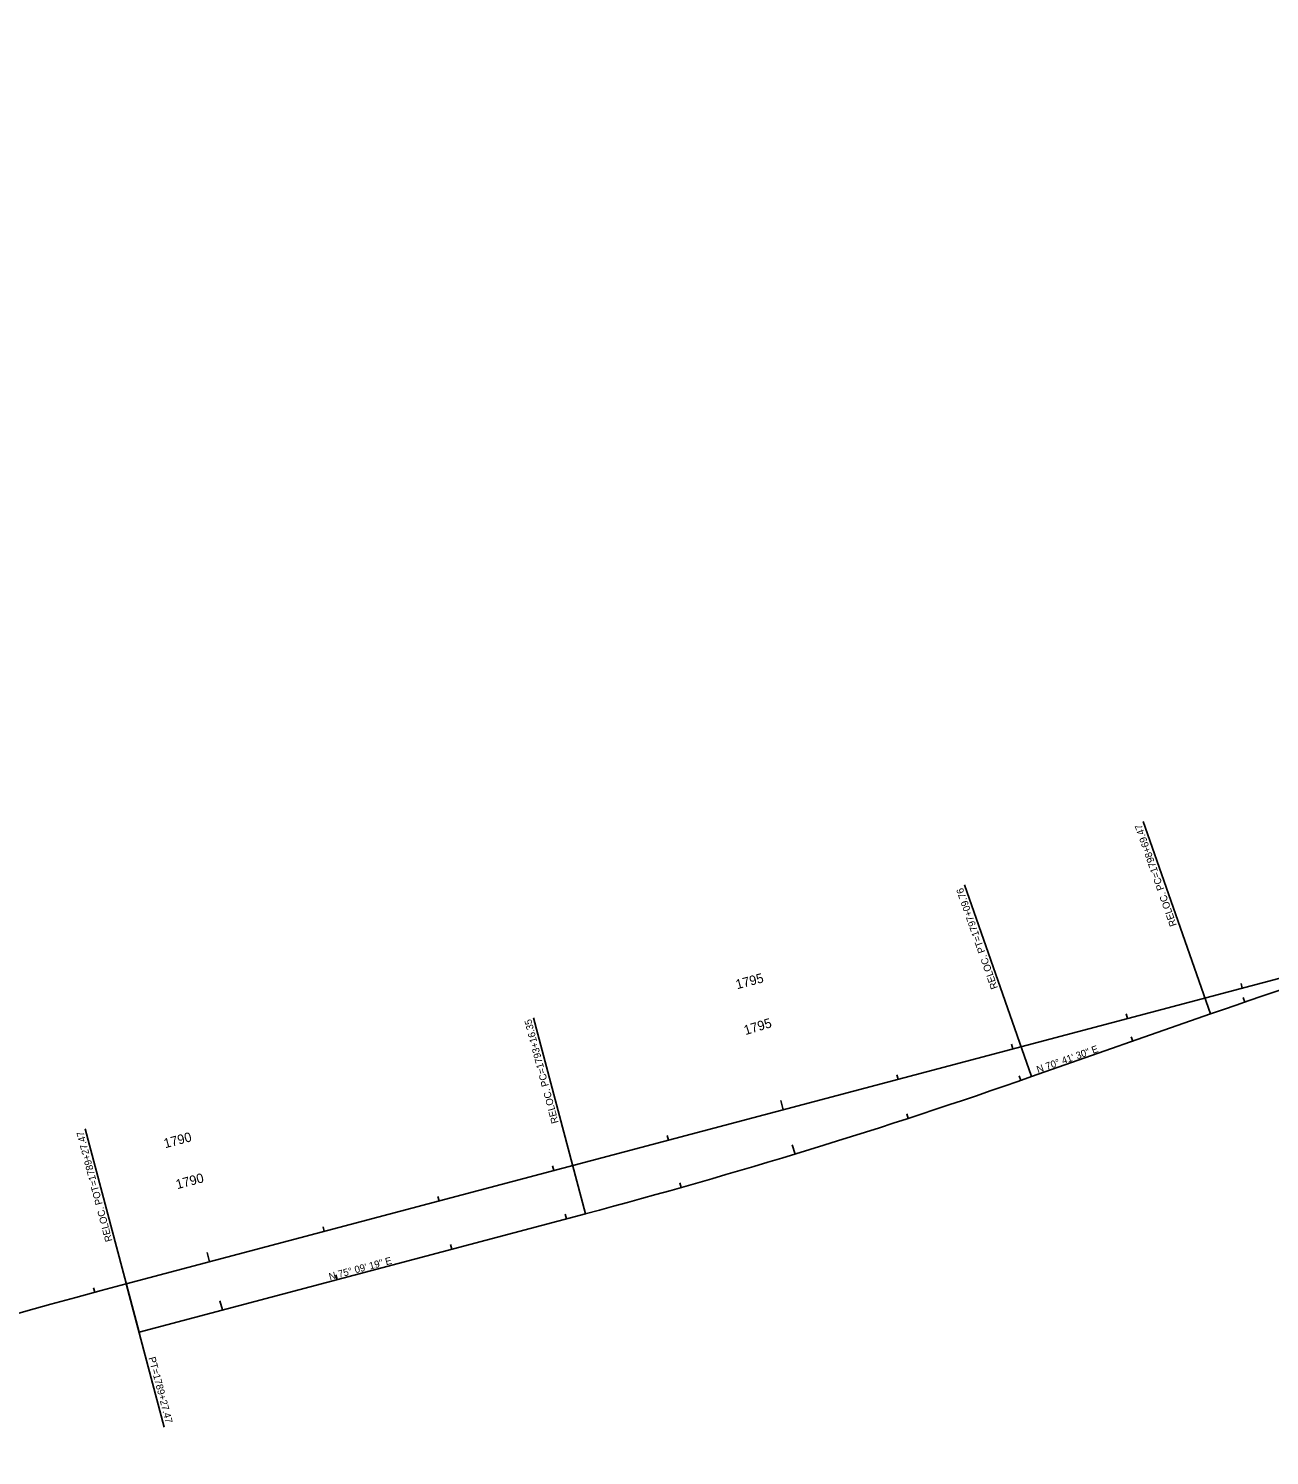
# Model space of a CAD drawing. Extents: x 2106154 to 2121963, y 864504 to 868517.
# Drawn here: x 2110006 to 2111052, y 867008 to 868210 of the extents above; entities that cross this region are included whole.
import ezdxf

# ---------------------------------------------------------------- set-up
doc = ezdxf.new("R2010")
doc.units = 0
for name, color, linetype in [('RD_HC_CL_Rel', 7, 'Continuous'), ('RD_HC_Data_Tic_Rel', 7, 'Continuous'), ('RD_HC_TX_Rel_Sta50', 7, 'Continuous'), ('RD_PD_EarthShd', 7, 'Continuous'), ('RD_PD_EOP', 7, 'Continuous'), ('RD_PD_Final_LnLine', 7, 'Continuous'), ('RD_Sketch1', 7, 'Continuous'), ('RD_Sketch10', 7, 'Continuous')]:
    doc.layers.add(name, color=color, linetype=linetype)

msp = doc.modelspace()

# ---------------------------------------------------------------- linework, layer by layer
at = {"layer": 'RD_HC_CL_Rel'}
msp.add_line((2110088.7, 867152.7), (2110120.7, 867032.1), dxfattribs=at)
at = {"layer": 'RD_HC_Data_Tic_Rel'}
for p, q in [((2110851.3, 867327.3), (2111002.1, 867380.1)), ((2110099.5, 867112.1), (2110475.4, 867211.8))]:
    msp.add_line(p, q, dxfattribs=at)
for centre, radius, start, end in [((2112556.1, 862944.4), 4700, 104.8448, 109.3083), ((2109181.5, 872093.2), 5050, 284.8448, 289.3083)]:
    msp.add_arc(centre, radius, start, end, dxfattribs=at)
at = {"layer": 'RD_HC_TX_Rel_Sta50'}
for p, q in [((2111002.1, 867380.1), (2110945.3, 867542.1)), ((2110851.3, 867327.3), (2110794.8, 867488.7)), ((2110475.4, 867211.8), (2110431.6, 867376.8)), ((2110099.5, 867112.1), (2110054.1, 867283.2))]:
    msp.add_line(p, q, dxfattribs=at)
at = {"layer": 'RD_PD_EarthShd'}
for p, q in [((2111028.8, 867401.9), (2111027.8, 867405.8)), ((2110932.1, 867376.3), (2110931.1, 867380.1)), ((2110835.5, 867350.7), (2110834.4, 867354.5)), ((2110738.8, 867325), (2110737.8, 867328.9)), ((2110642.1, 867299.4), (2110640.1, 867307.1)), ((2110545.5, 867273.8), (2110544.4, 867277.7)), ((2110448.8, 867248.2), (2110447.8, 867252)), ((2110352.1, 867222.6), (2110351.1, 867226.4)), ((2110255.5, 867196.9), (2110254.5, 867200.8)), ((2110158.8, 867171.3), (2110156.8, 867179)), ((2110062.2, 867145.6), (2110061.1, 867149.5))]:
    msp.add_line(p, q, dxfattribs=at)
at = {"layer": 'RD_PD_EOP'}
msp.add_line((2110088.7, 867152.7), (2114077.7, 868210), dxfattribs=at)
msp.add_arc((2111556.6, 861614.4), 5729.6, 104.84478, 132.83574, dxfattribs=at)
at = {"layer": 'RD_Sketch1'}
for p, q in [((2111030.9, 867390.1), (2111029.6, 867393.9)), ((2110936.5, 867357.1), (2110935.2, 867360.9)), ((2110842.1, 867324), (2110840.8, 867327.8)), ((2110747.4, 867292.1), (2110746.1, 867295.9)), ((2110652, 867262), (2110649.7, 867269.7)), ((2110556, 867233.9), (2110555, 867237.7)), ((2110459.6, 867207.6), (2110458.5, 867211.4)), ((2110362.9, 867182), (2110361.9, 867185.8)), ((2110266.2, 867156.3), (2110265.2, 867160.2)), ((2110169.6, 867130.7), (2110167.5, 867138.4))]:
    msp.add_line(p, q, dxfattribs=at)

# ---------------------------------------------------------------- texts
at = {"layer": 'RD_HC_CL_Rel'}
msp.add_text('PT=1789+27.47', height=6, rotation=284.8448, dxfattribs=at).set_placement((2110107.3, 867090.4))
at = {"layer": 'RD_HC_TX_Rel_Sta50'}
for s, rotation, p in [('RELOC. PC=1798+69.47', 109.3083, (2110973.7, 867454.9)), ('RELOC. PT=1797+09.76', 109.3083, (2110823, 867402.1)), ('RELOC. PC=1793+16.35', 104.8448, (2110452.9, 867288.6)), ('N 70%%d 41\' 30" E', 19.3083, (2110856.7, 867330.2)), ('RELOC. POT=1789+27.47', 104.8448, (2110077, 867189)), ('N 75%%d 09\' 19" E', 14.8448, (2110260.2, 867155.8))]:
    msp.add_text(s, height=6, rotation=rotation, dxfattribs=at).set_placement(p)
at = {"layer": 'RD_PD_Final_LnLine'}
for s, p in [('1795', (2110603.2, 867400.8)), ('1790', (2110121.4, 867266.9))]:
    msp.add_text(s, height=8, rotation=14.8448, dxfattribs=at).set_placement(p)
at = {"layer": 'RD_Sketch10'}
for s, rotation, p in [('1795', 16.9284, (2110610.3, 867362.2)), ('1790', 14.8448, (2110131.6, 867232.4))]:
    msp.add_text(s, height=8, rotation=rotation, dxfattribs=at).set_placement(p)

doc.saveas('drawing.dxf')
